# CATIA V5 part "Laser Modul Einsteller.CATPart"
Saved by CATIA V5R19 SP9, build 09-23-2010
Part number: Laser Modul Einsteller
Bounding box of the stored display mesh (mm): x -24 to 10, y -18 to 16, z -10 to 0
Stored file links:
  D:\Temporäre Sachen\Lasermodul KY-008 with mounting for adjustment\Laser Modul Einsteller.CATPart
  E:\Markus\Adruino\Tischkicker\CAD Modell\Halter Lasermodul.CATPart
  d:\Program Files\Dassault Systemes\B19\win_b64\reffiles\standard\MetricThickPitch.txt
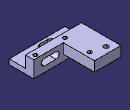
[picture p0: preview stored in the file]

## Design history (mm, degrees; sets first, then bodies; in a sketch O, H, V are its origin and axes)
Parameters
  LENGTH = 2.54 mm
Body1 (main body)
  Sketch1 on xy-plane, origin (0, 0, 0), H (1, 0, 0), V (0, 1, 0)
    line L1 (10, 16) -> (10, -18)
    line L2 (10, -18) -> (-24, -18)
    line L3 (-24, -18) -> (-24, 16)
    line L4 (-24, 16) -> (10, 16)
    distance V L1 = 10
    distance H L2 = 18
    distance H L4 = 16
    distance V L3 = 24
    vertical: L1 V, L3 V
    horizontal: L2 H, L4 H
  Pad1: profile Sketch1, direction (0, 0, -1), length 10
  Sketch2 on xy-plane, origin (0, 0, 0), H (1, 0, 0), V (0, 1, 0)
    line L1 (-8, -3) -> (10.7802, -3)
    line L2 (10.7802, -3) -> (10.7802, 23.1802)
    line L3 (10.7802, 23.1802) -> (-8, 23.1802)
    line L4 (-8, 23.1802) -> (-8, -3)
    distance L1 H = 3
    distance L4 V = 8
    horizontal: L1 H, L3 H
    vertical: L2 V, L4 V
  Pocket1: profile Sketch2, direction (0, 0, -1), length 12, opposite side length 4
  Sketch3 on xy-plane, origin (0, 0, 0), H (1, 0, 0), V (0, 1, 0)
    construction line L1 (-11, 10) -> (7, 10)
    construction line L2 (7, 10) -> (7, -5)
    construction line L3 (7, -5) -> (-11, -5)
    construction line L4 (-11, -5) -> (-11, 10)
    point P4 (-11, -5)
    point P5 (-19, 12)
    point P6 (-9, -14)
    distance L2 L4 = 18 (reference)
    distance H L1 = 10
    distance H L3 = 5
    distance V L2 = 7
    distance V L4 = 11
    distance H P5 = 12
    distance P5 V = 19
    distance P6 H = 14
    distance P6 V = 9
    horizontal: L1 H, L3 H
    vertical: L2 V, L4 V
  Sketch4 on end face of Pad1, origin (-10, -5, -10), H (1, 0, 0), V (0, -1, 0)
    point P1 (-1, 0)
    reference projected point E1 (-1, 0) from Sketch3.P4
    coincidence: E1 P1
  Hole1: placed by Sketch4, at (-11, -5, -10) direction (0, 0, 1), diameter 2.459, depth 20, threaded "M3", thread diameter 3, thread depth 15, pitch 0.5
  UserPattern1: of Hole1, copies 5, at the points of Sketch3
  Sketch5 on end face of Pad1, origin (-17, 12, -10), H (1, 0, 0), V (0, -1, 0)
    point P1 (-2, 0)
    reference projected point E1 (-2, 0) from Sketch3.P5
    coincidence: E1 P1
  Hole2: placed by Sketch5, at (-19, 12, -10) direction (0, 0, 1), diameter 3, depth 15
  Sketch6 on xy-plane, origin (0, 0, 0), H (1, 0, 0), V (0, 1, 0)
    construction line L1 (-7, -14) -> (-12, -14)
    point P1 (-7, -14)
    line L2 (-7, -16.5) -> (-12, -16.5)
    line L3 (-12, -11.5) -> (-7, -11.5)
    arc A1 centre (-12, -14) radius 2.5 from (-12, -16.5) to (-12, -11.5) cw
    arc A2 centre (-7, -14) radius 2.5 from (-7, -11.5) to (-7, -16.5) cw
    distance L1 L2 = 2.5
    distance V P1 = 7
    length L1 = 5
    distance L1 H = 14
    horizontal: L1 H
    tangency: A1 L2, A2 L2, A1 L3, A2 L3
  Pocket2: profile Sketch6, direction (0, 0, -1), length 20
  Sketch7 on zx-plane, origin (0, 0, 0), H (-1, 0, 0), V (0, 0, 1)
    construction line L1 (-3.5, -4.5) -> (3.5, -4.5)
    point P1 (-3.5, -4.5)
    point P2 (3.5, -4.5)
    line L2 (-3.5, -2.5) -> (3.5, -2.5)
    line L3 (3.5, -6.5) -> (-3.5, -6.5)
    arc A1 centre (3.5, -4.5) radius 2 from (3.5, -2.5) to (3.5, -6.5) cw
    arc A2 centre (-3.5, -4.5) radius 2 from (-3.5, -6.5) to (-3.5, -2.5) cw
    distance L1 L2 = 2
    distance H L1 = 4.5
    distance P1 P2 = 7
    horizontal: L1 H
    tangency: A1 L2, A2 L2, A1 L3, A2 L3
    symmetry: P2 P1 V
  Pocket3: profile Sketch7, direction (0, -1, 0), length 20
  Sketch8 on end face of Pad1, origin (0, 0, -10), H (1, 0, 0), V (0, -1, 0)
    line L1 (10.9716, 3) -> (-26.3713, 3)
    line L2 (-26.3713, 3) -> (-26.3713, -19.7413)
    line L3 (-26.3713, -19.7413) -> (10.9716, -19.7413)
    line L4 (10.9716, -19.7413) -> (10.9716, 3)
    distance H L1 = 3
    horizontal: L1 H, L3 H
    vertical: L2 V, L4 V
  Pocket4: profile Sketch8, direction (0, 0, 1), length 4
  Sketch9 on xy-plane, origin (0, 0, 0), H (1, 0, 0), V (0, 1, 0)
    line L1 (-26.705, -8) -> (11, -8)
    line L2 (14, -11) -> (14, -23.4108)
    line L3 (14, -23.4108) -> (-26.705, -23.4108)
    line L4 (-26.705, -23.4108) -> (-26.705, -8)
    arc A1 centre (11, -11) radius 3 from (11, -8) to (14, -11) cw
    distance H L1 = 8
    distance V L2 = 14
    radius A1 = 3
    horizontal: L1 H, L3 H
    vertical: L2 V, L4 V
    tangency: A1 L1, A1 L2
  Pocket5: profile Sketch9, direction (0, 0, -1), length 7
  Chamfer1: length 1, angle 5, on edge [end face of Pad1 | face of Pocket4 from Sketch8.L1]
  Sketch10 on xy-plane, origin (0, 0, 0), H (1, 0, 0), V (0, 1, 0)
    line L1 (-20, 8) -> (-14, 8)
    line L2 (-14, 8) -> (-14, -5)
    line L3 (-14, -5) -> (-20, -5)
    line L4 (-20, -5) -> (-20, 8)
    line L5 (18, -10) -> (-2, -10)
    line L6 (-2, -10) -> (-2, -20.605)
    line L7 (-2, -20.605) -> (18, -20.605)
    line L8 (18, -20.605) -> (18, -10)
    line L9 (-25.6823, -10) -> (-17, -10)
    line L10 (-17, -10) -> (-17, -19.6264)
    line L11 (-17, -19.6264) -> (-25.6823, -19.6264)
    line L12 (-25.6823, -19.6264) -> (-25.6823, -10)
    distance V L6 = 2
    length L5 = 20
    distance H L5 = 10
    length L8 = 10.605
    distance V L10 = 17
    length L11 = 8.6823
    distance L9 H = 10
    length L12 = 9.6264
    distance V L2 = 14
    length L1 = 6
    distance H L1 = 8
    distance H L3 = 5
    horizontal: L1 H, L3 H, L5 H, L7 H, L9 H, L11 H
    vertical: L2 V, L4 V, L6 V, L8 V, L10 V, L12 V
  Pocket6: profile Sketch10, direction (0, 0, -1), length 14, mirrored extent, deactivated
